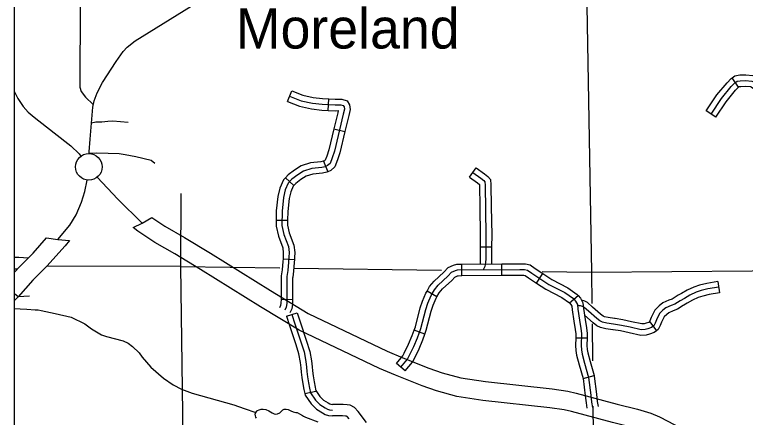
# Model space of a CAD drawing. Extents: x 1373862 to 1376999, y 1168398 to 1170455.
# Drawn here: x 1374675.3 to 1374867.5, y 1168643.6 to 1168749.6 of the extents above; entities that cross this region are included whole.
import ezdxf

# ---------------------------------------------------------------- set-up
doc = ezdxf.new("R2010")
doc.units = 0
for name, color, linetype in [('Level 10', 7, 'Continuous'), ('Level 24', 7, 'Continuous'), ('Level 31', 7, 'Continuous'), ('Level 32', 7, 'Continuous'), ('Level 35', 7, 'Continuous'), ('Level 37', 7, 'Continuous'), ('Level 45', 7, 'Continuous'), ('Level 46', 7, 'Continuous'), ('Level 5', 7, 'Continuous'), ('R_Draft', 7, 'Continuous')]:
    doc.layers.add(name, color=color, linetype=linetype)

msp = doc.modelspace()

# ---------------------------------------------------------------- linework, layer by layer
at = {"layer": 'Level 10'}
msp.add_line((1374676.24, 1168675.33), (1374675.34, 1168676.14), dxfattribs=at)
for points in [[(1374694.93, 1168713.03), (1374694.94, 1168713.5), (1374695.2, 1168716.86), (1374695.87, 1168725.24), (1374696.25, 1168726.94), (1374697.04, 1168729.04), (1374698.49, 1168731.73), (1374702.08, 1168737.3), (1374703.84, 1168739.89), (1374704.91, 1168741.03), (1374707.06, 1168742.69), (1374721.77, 1168751.84)], [(1374675.34, 1168729.32), (1374676.15, 1168727.51), (1374677.6, 1168725.41), (1374678.93, 1168723.92), (1374680.46, 1168722.63), (1374685.77, 1168718.54)], [(1374685.77, 1168718.54), (1374690.16, 1168715.12), (1374692.34, 1168712.99), (1374692.78, 1168712.36)], [(1374708.91, 1168694.72), (1374702.46, 1168701.03), (1374697.08, 1168706.84)], [(1374686.72, 1168690.4), (1374689.82, 1168694.16), (1374691.54, 1168696.93), (1374692.89, 1168700.24), (1374693.79, 1168703.04), (1374694.38, 1168706.06)], [(1374706.54, 1168693.56), (1374708.91, 1168694.72), (1374711.43, 1168696.19)], [(1374711.43, 1168696.19), (1374714.86, 1168693.93), (1374720.01, 1168690.98), (1374726.82, 1168686.81), (1374742.6, 1168676.96), (1374752.57, 1168670.98), (1374773.35, 1168661.04), (1374777.41, 1168659.31), (1374784.26, 1168656.57), (1374787.75, 1168655.34), (1374792.66, 1168654.02), (1374799.14, 1168653.04), (1374816.69, 1168651.11), (1374820.78, 1168650.5), (1374822.99, 1168649.98), (1374833.82, 1168647.07), (1374839.18, 1168645.75), (1374842.67, 1168644.69), (1374844.93, 1168643.77), (1374847.15, 1168642.61), (1374852.95, 1168639.5), (1374855.7, 1168638.48), (1374878.03, 1168631.81)], [(1374876.67, 1168627), (1374854.11, 1168633.74), (1374850.89, 1168634.93), (1374844.81, 1168638.19), (1374842.82, 1168639.24), (1374841, 1168639.98), (1374837.86, 1168640.93), (1374832.57, 1168642.23), (1374821.77, 1168645.13), (1374819.84, 1168645.58), (1374816.05, 1168646.15), (1374798.5, 1168648.08), (1374791.64, 1168649.11), (1374786.26, 1168650.56), (1374782.5, 1168651.89), (1374775.5, 1168654.69), (1374771.29, 1168656.49), (1374750.2, 1168666.57), (1374739.99, 1168672.69), (1374724.19, 1168682.55), (1374717.46, 1168686.68), (1374712.24, 1168689.67), (1374707.71, 1168692.65), (1374706.54, 1168693.56)], [(1374675.34, 1168681.81), (1374676.51, 1168683.12), (1374680.2, 1168686.86), (1374683.75, 1168690.83)], [(1374689.79, 1168690.2), (1374688.61, 1168688.76), (1374683.85, 1168683.44), (1374680.16, 1168679.69), (1374676.24, 1168675.33)], [(1374683.75, 1168690.83), (1374686.72, 1168690.4), (1374689.79, 1168690.2)], [(1374676.24, 1168675.33), (1374675.34, 1168674.33)]]:
    msp.add_lwpolyline(points, dxfattribs=at)
at = {"layer": 'Level 24'}
msp.add_circle((1374694.85, 1168709.53), 3.5, dxfattribs=at)
at = {"layer": 'Level 31'}
for points in [[(1374692.68, 1168757.47), (1374692.6, 1168746.91)], [(1374692.6, 1168746.91), (1374692.52, 1168736.35)], [(1374692.52, 1168736.35), (1374692.48, 1168730.56), (1374692.83, 1168729.38), (1374693.94, 1168727.85), (1374696.02, 1168725.92)], [(1374675.34, 1168685.74), (1374676.46, 1168685.74), (1374678.92, 1168685.56)], [(1374675.34, 1168682.74), (1374676.14, 1168682.74)]]:
    msp.add_lwpolyline(points, dxfattribs=at)
at = {"layer": 'Level 32'}
for p, q in [((1374865.74, 1168730.55), (1374864.03, 1168733.02)), ((1374747.12, 1168726.72), (1374748.2, 1168729.52)), ((1374757.83, 1168724.42), (1374757.99, 1168727.42)), ((1374859.74, 1168722.59), (1374857.24, 1168724.25)), ((1374759.29, 1168719.57), (1374762.21, 1168718.88)), ((1374756.53, 1168711.02), (1374757.73, 1168708.27)), ((1374746.57, 1168706.68), (1374748.78, 1168704.65)), ((1374744.14, 1168695.5), (1374747.14, 1168695.48)), ((1374745.92, 1168685.29), (1374748.92, 1168685.15)), ((1374792.95, 1168680.91), (1374792.93, 1168683.91)), ((1374803.51, 1168681.01), (1374803.49, 1168684.01)), ((1374812.56, 1168678.95), (1374814.21, 1168681.46)), ((1374786.41, 1168675.35), (1374783.79, 1168676.79)), ((1374821.26, 1168673.72), (1374823.5, 1168675.72)), ((1374745.43, 1168674.74), (1374748.43, 1168674.63)), ((1374783.23, 1168665.54), (1374780.42, 1168666.59)), ((1374822.9, 1168664.58), (1374825.9, 1168664.51)), ((1374778.05, 1168655.85), (1374775.76, 1168657.79)), ((1374824.83, 1168653.82), (1374827.72, 1168654.63))]:
    msp.add_line(p, q, dxfattribs=at)
for points in [[(1374864.03, 1168733.02), (1374864.76, 1168733.53), (1374866.04, 1168733.73), (1374867.61, 1168733.78), (1374869.48, 1168733.62), (1374870.39, 1168733.32), (1374871.17, 1168732.78), (1374871.98, 1168732.41), (1374872.88, 1168732.21), (1374873.47, 1168732.21), (1374874.39, 1168732.38), (1374874.42, 1168732.39)], [(1374857.24, 1168724.25), (1374860.05, 1168728.47), (1374862.69, 1168731.7), (1374863.77, 1168732.84), (1374864.03, 1168733.02)], [(1374858.49, 1168723.42), (1374861.26, 1168727.58), (1374863.81, 1168730.71), (1374864.75, 1168731.69), (1374865.33, 1168732.1), (1374866.18, 1168732.23), (1374867.57, 1168732.28), (1374869.18, 1168732.14), (1374869.71, 1168731.96), (1374870.43, 1168731.47), (1374871.5, 1168730.98), (1374872.71, 1168730.71), (1374873.61, 1168730.71), (1374874.81, 1168730.93), (1374876.15, 1168731.47), (1374877.54, 1168731.74), (1374881.16, 1168732.1), (1374883.44, 1168732.32), (1374885.28, 1168732.32), (1374888.5, 1168731.87), (1374891.39, 1168731.52), (1374892.47, 1168731.43), (1374894.02, 1168731.24)], [(1374748.2, 1168729.52), (1374751.14, 1168728.39), (1374753.88, 1168727.78), (1374756.34, 1168727.5), (1374757.99, 1168727.42)], [(1374859.74, 1168722.59), (1374862.47, 1168726.69), (1374864.94, 1168729.72), (1374865.73, 1168730.55), (1374865.74, 1168730.55)], [(1374865.74, 1168730.55), (1374865.9, 1168730.67), (1374866.32, 1168730.74), (1374867.53, 1168730.77), (1374868.87, 1168730.66), (1374869.04, 1168730.61), (1374869.69, 1168730.16), (1374871.02, 1168729.55), (1374872.55, 1168729.21), (1374873.74, 1168729.21), (1374875.23, 1168729.49), (1374875.53, 1168729.61)], [(1374747.66, 1168728.12), (1374750.71, 1168726.94), (1374753.64, 1168726.3), (1374756.22, 1168726.01), (1374759.65, 1168725.83), (1374761.17, 1168725.86), (1374761.76, 1168725.68), (1374761.96, 1168725.33), (1374762.08, 1168724.72), (1374761.75, 1168723.44), (1374759.44, 1168713.65), (1374758.88, 1168711.89), (1374758.29, 1168710.45), (1374757.65, 1168709.87), (1374756.97, 1168709.57), (1374756.09, 1168709.4), (1374753.46, 1168709.13), (1374751.35, 1168708.43), (1374749.79, 1168707.43), (1374748.27, 1168706.32), (1374747.3, 1168705.26), (1374746.51, 1168703.47), (1374746.04, 1168701.45), (1374745.66, 1168697.87), (1374745.63, 1168694.08), (1374746.13, 1168691.76), (1374747.33, 1168688.62), (1374747.51, 1168686.98), (1374747.45, 1168685.75), (1374747.39, 1168684.49), (1374747.15, 1168682.23), (1374746.96, 1168680.66), (1374746.93, 1168680.34), (1374746.95, 1168675.15), (1374746.89, 1168673.56), (1374746.74, 1168672.59), (1374746.37, 1168671.78)], [(1374747.12, 1168726.72), (1374750.27, 1168725.5), (1374753.39, 1168724.82), (1374756.09, 1168724.51), (1374757.83, 1168724.42)], [(1374757.99, 1168727.42), (1374759.67, 1168727.33), (1374761.38, 1168727.36), (1374762.75, 1168726.95), (1374763.39, 1168725.87), (1374763.62, 1168724.67), (1374763.21, 1168723.08), (1374762.21, 1168718.88)], [(1374757.83, 1168724.42), (1374759.62, 1168724.33), (1374760.44, 1168724.35), (1374760.3, 1168723.8), (1374759.29, 1168719.57)], [(1374695.55, 1168721.15), (1374696.72, 1168721.39), (1374698.29, 1168721.39), (1374699.87, 1168721.56), (1374701.15, 1168721.62), (1374705.16, 1168721.27)], [(1374759.29, 1168719.57), (1374757.99, 1168714.05), (1374757.47, 1168712.4), (1374757.03, 1168711.33), (1374756.82, 1168711.14), (1374756.53, 1168711.02)], [(1374762.21, 1168718.88), (1374760.88, 1168713.25), (1374760.29, 1168711.38), (1374759.55, 1168709.57), (1374758.47, 1168708.59), (1374757.73, 1168708.27)], [(1374694.94, 1168713.16), (1374696.97, 1168713.22), (1374699.96, 1168713.16), (1374702.86, 1168713.06), (1374704.42, 1168712.84), (1374707.22, 1168712.25), (1374711.21, 1168711.32), (1374712.24, 1168710.51)], [(1374756.53, 1168711.02), (1374756.52, 1168711.01), (1374755.87, 1168710.88), (1374753.14, 1168710.61), (1374750.69, 1168709.79), (1374748.94, 1168708.67), (1374747.26, 1168707.44), (1374746.57, 1168706.68)], [(1374757.73, 1168708.27), (1374757.43, 1168708.13), (1374756.32, 1168707.91), (1374753.77, 1168707.66), (1374752, 1168707.06), (1374750.64, 1168706.19), (1374749.27, 1168705.19), (1374748.78, 1168704.65)], [(1374746.57, 1168706.68), (1374746.03, 1168706.09), (1374745.08, 1168703.95), (1374744.56, 1168701.7), (1374744.16, 1168697.96), (1374744.14, 1168695.5)], [(1374748.78, 1168704.65), (1374748.57, 1168704.43), (1374747.94, 1168702.99), (1374747.52, 1168701.2), (1374747.16, 1168697.79), (1374747.14, 1168695.48)], [(1374744.14, 1168695.5), (1374744.13, 1168693.92), (1374744.69, 1168691.33), (1374745.86, 1168688.27), (1374746, 1168686.93), (1374745.95, 1168685.82), (1374745.92, 1168685.29)], [(1374747.14, 1168695.48), (1374747.13, 1168694.23), (1374747.57, 1168692.19), (1374748.8, 1168688.97), (1374749.01, 1168687.02), (1374748.95, 1168685.68), (1374748.92, 1168685.15)], [(1374745.92, 1168685.29), (1374745.89, 1168684.6), (1374745.66, 1168682.4), (1374745.47, 1168680.83), (1374745.43, 1168680.4), (1374745.45, 1168675.17), (1374745.43, 1168674.74)], [(1374748.92, 1168685.15), (1374748.89, 1168684.37), (1374748.65, 1168682.06), (1374748.46, 1168680.5), (1374748.43, 1168680.27), (1374748.45, 1168675.12), (1374748.43, 1168674.63)], [(1374783.79, 1168676.79), (1374784.47, 1168678.04), (1374785.64, 1168679.46), (1374788.19, 1168681.82), (1374789.37, 1168683.04), (1374790.78, 1168683.7), (1374791.63, 1168683.9), (1374792.93, 1168683.91)], [(1374792.93, 1168683.91), (1374803.49, 1168684.01)], [(1374803.49, 1168684.01), (1374808.17, 1168684.05), (1374809.65, 1168684.01), (1374810.88, 1168683.72), (1374812.21, 1168682.77), (1374814.21, 1168681.46)], [(1374776.91, 1168656.82), (1374778.69, 1168658.94), (1374779.13, 1168659.79), (1374780.32, 1168662.27), (1374781.27, 1168664.57), (1374782.16, 1168666.97), (1374783.46, 1168671.98), (1374784, 1168673.7), (1374784.86, 1168675.64), (1374785.72, 1168677.19), (1374786.73, 1168678.43), (1374789.24, 1168680.75), (1374790.26, 1168681.8), (1374791.27, 1168682.27), (1374791.81, 1168682.4), (1374808.16, 1168682.55), (1374809.46, 1168682.52), (1374810.25, 1168682.33), (1374811.36, 1168681.53), (1374815.83, 1168678.6), (1374820, 1168676.43), (1374822.27, 1168674.85), (1374822.88, 1168674.16), (1374823.33, 1168673.31), (1374823.48, 1168672.1), (1374823.87, 1168669.16), (1374824.27, 1168666.98), (1374824.43, 1168665.64), (1374824.36, 1168662.51), (1374824.41, 1168661.35), (1374824.59, 1168660.28), (1374825.25, 1168657.87), (1374826.3, 1168654.13), (1374826.84, 1168649.49), (1374827.09, 1168647.62), (1374827.28, 1168646.24)], [(1374814.21, 1168681.46), (1374816.59, 1168679.9), (1374820.78, 1168677.71), (1374823.27, 1168675.98), (1374823.5, 1168675.72)], [(1374786.41, 1168675.35), (1374786.96, 1168676.35), (1374787.83, 1168677.4), (1374790.29, 1168679.67), (1374791.14, 1168680.55), (1374791.77, 1168680.85), (1374791.99, 1168680.9), (1374792.95, 1168680.91)], [(1374792.95, 1168680.91), (1374803.51, 1168681.01)], [(1374803.51, 1168681.01), (1374808.14, 1168681.05), (1374809.26, 1168681.02), (1374809.62, 1168680.94), (1374810.51, 1168680.29), (1374812.56, 1168678.95)], [(1374812.56, 1168678.95), (1374815.07, 1168677.31), (1374819.22, 1168675.14), (1374821.27, 1168673.72), (1374821.26, 1168673.72)], [(1374780.42, 1168666.59), (1374780.73, 1168667.42), (1374782.02, 1168672.4), (1374782.6, 1168674.23), (1374783.52, 1168676.3), (1374783.79, 1168676.79)], [(1374823.5, 1168675.72), (1374824.13, 1168675.02), (1374824.78, 1168673.76), (1374824.97, 1168672.3), (1374825.35, 1168669.39), (1374825.75, 1168667.2), (1374825.93, 1168665.72), (1374825.9, 1168664.51)], [(1374745.43, 1168674.74), (1374745.39, 1168673.7), (1374745.29, 1168673.03), (1374745.01, 1168672.4)], [(1374748.43, 1168674.63), (1374748.39, 1168673.42), (1374748.2, 1168672.16), (1374747.74, 1168671.16)], [(1374783.23, 1168665.54), (1374783.6, 1168666.52), (1374784.91, 1168671.57), (1374785.41, 1168673.17), (1374786.21, 1168674.97), (1374786.41, 1168675.35)], [(1374821.26, 1168673.72), (1374821.64, 1168673.3), (1374821.87, 1168672.85), (1374822, 1168671.91), (1374822.38, 1168668.93), (1374822.78, 1168666.75), (1374822.93, 1168665.57), (1374822.9, 1168664.58)], [(1374775.76, 1168657.79), (1374777.43, 1168659.77), (1374777.78, 1168660.46), (1374778.95, 1168662.88), (1374779.87, 1168665.12), (1374780.42, 1168666.59)], [(1374778.05, 1168655.85), (1374779.94, 1168658.1), (1374780.47, 1168659.12), (1374781.69, 1168661.66), (1374782.67, 1168664.02), (1374783.23, 1168665.54)], [(1374822.9, 1168664.58), (1374822.86, 1168662.5), (1374822.91, 1168661.19), (1374823.13, 1168659.95), (1374823.81, 1168657.47), (1374824.83, 1168653.82)], [(1374825.9, 1168664.51), (1374825.86, 1168662.53), (1374825.9, 1168661.51), (1374826.06, 1168660.6), (1374826.7, 1168658.27), (1374827.72, 1168654.63)], [(1374827.72, 1168654.63), (1374827.78, 1168654.42), (1374828.33, 1168649.68), (1374828.58, 1168647.82), (1374828.76, 1168646.44)], [(1374824.82, 1168653.84), (1374825.35, 1168649.31), (1374825.61, 1168647.42), (1374825.79, 1168646.04)]]:
    msp.add_lwpolyline(points, dxfattribs=at)
at = {"layer": 'Level 35'}
for points in [[(1374675.34, 1168672.26), (1374676.8, 1168672.13), (1374678.52, 1168672.09), (1374680.74, 1168671.89), (1374681.51, 1168671.87), (1374682.35, 1168671.73), (1374685.99, 1168670.91)], [(1374685.99, 1168670.91), (1374690.21, 1168669.95), (1374693.8, 1168668.25), (1374695.57, 1168666.87), (1374698.17, 1168665.33), (1374699.5, 1168664.86), (1374703.84, 1168663.76), (1374705.23, 1168663.17), (1374706.37, 1168662.28), (1374708.13, 1168660.6), (1374708.9, 1168659.47), (1374711.2, 1168656.86), (1374714.45, 1168653.92), (1374717.01, 1168652.17), (1374719.19, 1168651.06), (1374721.99, 1168649.93), (1374733, 1168646.89), (1374735.67, 1168645.97), (1374738.79, 1168644.89)], [(1374738.93, 1168643.35), (1374738.77, 1168643.65), (1374738.65, 1168643.97), (1374738.63, 1168644.41), (1374738.79, 1168644.89), (1374739.13, 1168645.35), (1374739.23, 1168645.39), (1374739.69, 1168645.62), (1374740.21, 1168645.74), (1374740.67, 1168645.78), (1374741.39, 1168645.66), (1374742.19, 1168645.3), (1374743.05, 1168644.82), (1374743.63, 1168644.56), (1374744.05, 1168644.46), (1374744.5, 1168644.52), (1374745.06, 1168644.82), (1374745.42, 1168645.16), (1374745.86, 1168645.62), (1374746.26, 1168645.8), (1374746.76, 1168645.8), (1374747.3, 1168645.7), (1374747.98, 1168645.34), (1374748.62, 1168645.04), (1374749.26, 1168644.92), (1374749.64, 1168644.86), (1374750.28, 1168644.52), (1374751.04, 1168644.06), (1374751.3, 1168643.94), (1374751.84, 1168643.66), (1374755.05, 1168642.45)]]:
    msp.add_lwpolyline(points, dxfattribs=at)
at = {"layer": 'Level 37'}
msp.add_lwpolyline([(1374679.24, 1168675.49), (1374676.24, 1168675.33)], dxfattribs=at)
at = {"layer": 'Level 45'}
for p, q in [((1374794.97, 1168706.84), (1374796.72, 1168709.28)), ((1374797.79, 1168688.52), (1374800.79, 1168688.5)), ((1374860.28, 1168679.33), (1374860.74, 1168676.37)), ((1374746.81, 1168670.2), (1374749.66, 1168671.13)), ((1374842.37, 1168668.79), (1374844.12, 1168666.36)), ((1374751.66, 1168649.86), (1374754.58, 1168650.54))]:
    msp.add_line(p, q, dxfattribs=at)
for points in [[(1374796.72, 1168709.28), (1374798.87, 1168707.74), (1374799.79, 1168707.01), (1374800.46, 1168706.19), (1374800.61, 1168704.82), (1374800.69, 1168699.09)], [(1374794.97, 1168706.84), (1374797.06, 1168705.34), (1374797.58, 1168704.93), (1374797.61, 1168704.63), (1374797.69, 1168699.05)], [(1374795.84, 1168708.06), (1374797.97, 1168706.54), (1374798.73, 1168705.93), (1374799.02, 1168705.59), (1374799.11, 1168704.73), (1374799.3, 1168691.58), (1374799.27, 1168685.31), (1374799.17, 1168684.39), (1374799.02, 1168683.34), (1374798.6, 1168682.46)], [(1374797.69, 1168699.05), (1374797.8, 1168691.58), (1374797.79, 1168688.52)], [(1374800.69, 1168699.09), (1374800.8, 1168691.59), (1374800.79, 1168688.5)], [(1374797.79, 1168688.52), (1374797.76, 1168683.95)], [(1374800.79, 1168688.5), (1374800.76, 1168683.98)], [(1374860.51, 1168677.85), (1374857.66, 1168677.4), (1374855.88, 1168676.96), (1374854.55, 1168676.52), (1374852.9, 1168675.75), (1374851.47, 1168674.93), (1374850.36, 1168674.29), (1374848.96, 1168673.4), (1374847.98, 1168673.02), (1374846.61, 1168672.45), (1374845.82, 1168671.82), (1374844.93, 1168670.93), (1374844.1, 1168669.31), (1374843.75, 1168668.39), (1374843.41, 1168667.69), (1374842.83, 1168667.28), (1374841.88, 1168666.93), (1374841.18, 1168666.74), (1374840.14, 1168666.67), (1374837.25, 1168667.31), (1374834.96, 1168667.82), (1374832.87, 1168668.16), (1374831.12, 1168668.39), (1374829.92, 1168668.67), (1374829.28, 1168668.99), (1374828.46, 1168669.63), (1374826.3, 1168671.53), (1374825.16, 1168672.55), (1374824.71, 1168672.77), (1374824.17, 1168672.93), (1374823.38, 1168672.93)], [(1374860.28, 1168679.33), (1374857.36, 1168678.88), (1374855.46, 1168678.4), (1374853.99, 1168677.91), (1374852.2, 1168677.09), (1374850.72, 1168676.23), (1374849.88, 1168675.75)], [(1374849.88, 1168675.75), (1374849.58, 1168675.58), (1374848.28, 1168674.75), (1374847.42, 1168674.41), (1374845.84, 1168673.75), (1374844.82, 1168672.94), (1374843.7, 1168671.82), (1374842.73, 1168669.92), (1374842.38, 1168668.99), (1374842.23, 1168668.69), (1374842.37, 1168668.79)], [(1374860.74, 1168676.37), (1374857.95, 1168675.93), (1374856.3, 1168675.52), (1374855.1, 1168675.12), (1374853.59, 1168674.42), (1374852.21, 1168673.63), (1374851.37, 1168673.15)], [(1374833.27, 1168669.62), (1374833.09, 1168669.65), (1374831.39, 1168669.87), (1374830.43, 1168670.09), (1374830.08, 1168670.27), (1374829.41, 1168670.78), (1374827.29, 1168672.65), (1374826.01, 1168673.8), (1374825.26, 1168674.17), (1374824.44, 1168674.41)], [(1374851.37, 1168673.15), (1374851.13, 1168673.01), (1374849.64, 1168672.06), (1374848.54, 1168671.63), (1374847.38, 1168671.15), (1374846.82, 1168670.7), (1374846.16, 1168670.03), (1374845.48, 1168668.7), (1374845.13, 1168667.78), (1374844.58, 1168666.69), (1374844.12, 1168666.36)], [(1374746.81, 1168670.2), (1374747.6, 1168667.78), (1374749.27, 1168662.76), (1374749.99, 1168660.44), (1374750.02, 1168660.32)], [(1374748.23, 1168670.67), (1374749.02, 1168668.25), (1374750.7, 1168663.22), (1374751.45, 1168660.81), (1374751.96, 1168658.28), (1374752.07, 1168656.8), (1374752.2, 1168655.67), (1374752.39, 1168654.31), (1374752.61, 1168652.7), (1374752.88, 1168651.26), (1374753.16, 1168650.06), (1374754.45, 1168648.1), (1374755.64, 1168646.95), (1374757.03, 1168646.1), (1374757.65, 1168645.78), (1374758.18, 1168645.59), (1374758.95, 1168645.53)], [(1374749.66, 1168671.13), (1374750.45, 1168668.72), (1374752.13, 1168663.68), (1374752.9, 1168661.18), (1374752.96, 1168660.92)], [(1374832.78, 1168666.66), (1374832.65, 1168666.68), (1374830.86, 1168666.91), (1374829.4, 1168667.25), (1374828.48, 1168667.71), (1374827.5, 1168668.47), (1374825.21, 1168670.5)], [(1374842.37, 1168668.79), (1374842.12, 1168668.61), (1374841.43, 1168668.36), (1374840.94, 1168668.22), (1374840.25, 1168668.18), (1374837.57, 1168668.77), (1374835.25, 1168669.29), (1374833.27, 1168669.62)], [(1374844.12, 1168666.36), (1374843.55, 1168665.94), (1374842.34, 1168665.5), (1374841.43, 1168665.25), (1374840.02, 1168665.16), (1374836.92, 1168665.84), (1374834.68, 1168666.34), (1374832.78, 1168666.66)], [(1374750.02, 1168660.32), (1374750.47, 1168658.08), (1374750.57, 1168656.67), (1374750.71, 1168655.48), (1374750.9, 1168654.1), (1374751.13, 1168652.46), (1374751.41, 1168650.95), (1374751.66, 1168649.86)], [(1374752.96, 1168660.92), (1374753.45, 1168658.48), (1374753.56, 1168656.94), (1374753.68, 1168655.86), (1374753.87, 1168654.51), (1374754.09, 1168652.94), (1374754.35, 1168651.57), (1374754.58, 1168650.54)]]:
    msp.add_lwpolyline(points, dxfattribs=at)
at = {"layer": 'Level 46'}
for points in [[(1374754.56, 1168650.66), (1374755.61, 1168649.06), (1374756.57, 1168648.15), (1374757.77, 1168647.4), (1374758.25, 1168647.16), (1374758.5, 1168647.07), (1374759.06, 1168647.03)], [(1374751.66, 1168649.86), (1374751.76, 1168649.46), (1374753.29, 1168647.13), (1374754.72, 1168645.76), (1374756.29, 1168644.79), (1374757.05, 1168644.4), (1374757.87, 1168644.1), (1374758.84, 1168644.03)], [(1374767.91, 1168642.21), (1374765.65, 1168645.11), (1374764.7, 1168646.23), (1374763.54, 1168646.81), (1374762.76, 1168646.94), (1374761.74, 1168647.03), (1374758.95, 1168647.03)], [(1374763.32, 1168643.22), (1374762.81, 1168643.82), (1374762.6, 1168643.92), (1374762.37, 1168643.96), (1374761.59, 1168644.03), (1374758.95, 1168644.03)]]:
    msp.add_lwpolyline(points, dxfattribs=at)
at = {"layer": 'Level 5'}
for points in [[(1374825.24, 1168787.11), (1374827.03, 1168681.84)], [(1374719.06, 1168702.53), (1374718.99, 1168683.28)], [(1374718.99, 1168683.28), (1374683.77, 1168683.36)], [(1374718.99, 1168683.28), (1374720.26, 1168586.75)], [(1374718.99, 1168683.28), (1374745.06, 1168682.93)], [(1374748.74, 1168682.89), (1374787.56, 1168682.37)], [(1374814.1, 1168682.01), (1374827.03, 1168681.84)], [(1374827.03, 1168681.84), (1374932.65, 1168682.72)], [(1374827.03, 1168681.84), (1374827.13, 1168673.6)], [(1374827.19, 1168668.19), (1374827.3, 1168658.46)], [(1374827.44, 1168646.52), (1374828.25, 1168576.43)]]:
    msp.add_lwpolyline(points, dxfattribs=at)
at = {"layer": 'R_Draft'}
msp.add_lwpolyline([(1374675.34, 1169579.43), (1376182.76, 1169579.43), (1376182.76, 1168562.99), (1374675.34, 1168562.99)], close=True, dxfattribs=at)

# ---------------------------------------------------------------- texts
at = {"layer": 'Level 24'}
msp.add_text('Moreland', height=10.56, dxfattribs=at).set_placement((1374733.51, 1168740.7))

doc.saveas('drawing.dxf')
